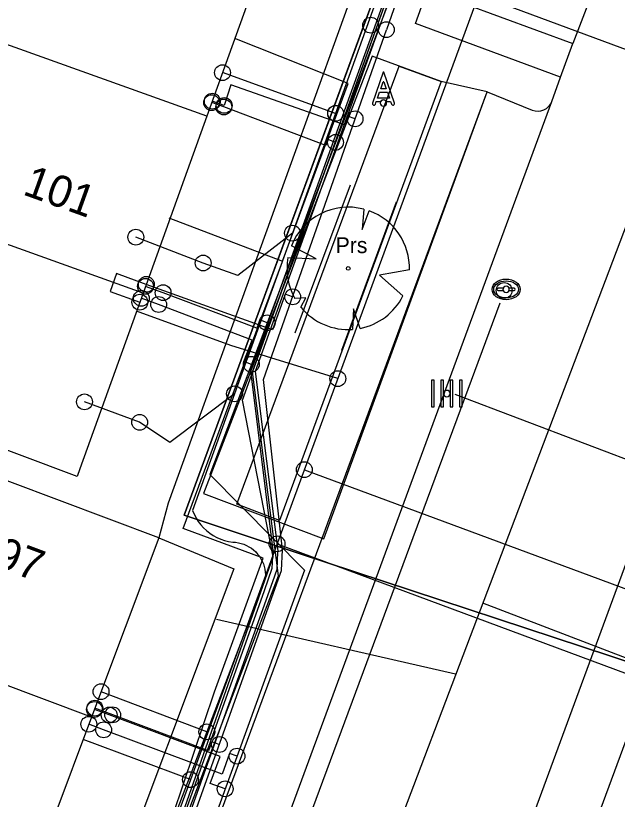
# Model space of a CAD drawing. Extents: x 192672 to 192910, y 446344 to 446512.
# Drawn here: x 192830.88 to 192849.9, y 446414.08 to 446438.86 of the extents above; entities that cross this region are included whole.
import ezdxf

# ---------------------------------------------------------------- set-up
doc = ezdxf.new("R2010")
doc.units = 0
for name, color, linetype in [('205134 wortelgeleidingsscherm', 7, 'Continuous'), ('B-GV-KG-GRENS_WERKGRENS-G', 7, 'Continuous'), ('B-OI-KL-()_MANTELBUIS_WATER-G', 7, 'Continuous'), ('B-OI-KL-()_OVERIG_RIOOLVRIJVERVAL-S', 7, 'Continuous'), ('B-OI-KL-()_PUNTVANLEVERING_WATER-S', 7, 'Continuous'), ('B-OI-KL-BUISLEIDING_OLIEGASCHEMICALIEN_GASLAGEDRUK-G', 7, 'Continuous'), ('B-OI-KL-DATA-G', 7, 'Continuous'), ('B-OI-KL-DATA_DUCT-G', 7, 'Continuous'), ('B-OI-KL-DATA_GTWP-S', 7, 'Continuous'), ('B-OI-KL-DATA_KABELBED-G', 7, 'Continuous'), ('B-OI-KL-DATA_MANTELBUIS-G', 7, 'Continuous'), ('B-OI-KL-DATA_MOF-S', 7, 'Continuous'), ('B-OI-KL-ET_LS-G', 7, 'Continuous'), ('B-OI-KL-ET_LS_AARDING-S', 7, 'Continuous'), ('B-OI-KL-ET_LS_DELIVERYPOINT-S', 7, 'Continuous'), ('B-OI-KL-ET_LS_MOF-S', 7, 'Continuous'), ('B-OI-KL-ET_MS-G', 7, 'Continuous'), ('B-OI-KL-GAS_LD_AFTAKZADEL-S', 7, 'Continuous'), ('B-OI-KL-GAS_LD_DELIVERYPOINT-S', 7, 'Continuous'), ('B-OI-KL-GAS_LD_OVERGANGSSTUK-S', 7, 'Continuous'), ('B-OI-KL-WATER-G', 7, 'Continuous'), ('B-OI-RI-RIOOLVRIJVERVAL-G', 7, 'Continuous'), ('bovenleidingmast', 7, 'Continuous'), ('Default', 7, 'Continuous'), ('huisnummerreeks BGT', 7, 'Continuous'), ('inspectie-   rioolput', 7, 'Continuous'), ('kant open verharding', 7, 'Continuous'), ('kant verharding', 7, 'Continuous'), ('kolk', 7, 'Continuous'), ('N-GV-GR-BOOM-S', 7, 'Continuous'), ('pand op maaiveld vlak', 7, 'Continuous'), ('TEKST', 7, 'Continuous'), ('verkeerseiland - berm', 7, 'Continuous')]:
    doc.layers.add(name, color=color, linetype=linetype)

# ---------------------------------------------------------------- blocks, each defined once
blk = doc.blocks.new('B-OI-KL-ET_LS_AARDING-S')
at = {"layer": 'Default'}
blk.add_circle((0, 0), 0.25, dxfattribs=at)
blk = doc.blocks.new('B-OI-KL-GAS_LD_AFTAKZADEL-S')
at = {"layer": 'Default'}
blk.add_circle((0, 0), 0.25, dxfattribs=at)
blk = doc.blocks.new('B-OI-KL-GAS_LD_DELIVERYPOINT-S')
at = {"layer": 'Default'}
blk.add_circle((0, 0), 0.25, dxfattribs=at)
blk = doc.blocks.new('B-OI-KL-GAS_LD_OVERGANGSSTUK-S')
at = {"layer": 'Default'}
blk.add_circle((0, 0), 0.25, dxfattribs=at)
blk = doc.blocks.new('B-OI-KL-ET_LS_DELIVERYPOINT-S')
at = {"layer": 'Default'}
blk.add_circle((0, 0), 0.25, dxfattribs=at)
blk = doc.blocks.new('B-OI-KL-ET_LS_MOF-S')
at = {"layer": 'Default'}
blk.add_circle((0, 0), 0.25, dxfattribs=at)
blk = doc.blocks.new('B-OI-KL-()_OVERIG_RIOOLVRIJVERVAL-S')
at = {"layer": 'Default'}
blk.add_circle((0, 0), 0.25, dxfattribs=at)
blk = doc.blocks.new('B-OI-KL-()_PUNTVANLEVERING_WATER-S')
at = {"layer": 'Default'}
blk.add_circle((0, 0), 0.25, dxfattribs=at)
blk = doc.blocks.new('B-OI-KL-DATA_GTWP-S')
at = {"layer": 'Default'}
blk.add_circle((0, 0), 0.25, dxfattribs=at)
blk = doc.blocks.new('B-OI-KL-DATA_MOF-S')
at = {"layer": 'Default'}
blk.add_circle((0, 0), 0.25, dxfattribs=at)

msp = doc.modelspace()

# ---------------------------------------------------------------- linework, layer by layer
at = {"layer": '205134 wortelgeleidingsscherm'}
for p, q in [((192839.712, 446428.827), (192841.461, 446433.511)), ((192841.184, 446428.282), (192842.919, 446432.971))]:
    msp.add_line(p, q, dxfattribs=at)
at = {"layer": 'B-GV-KG-GRENS_WERKGRENS-G'}
msp.add_lwpolyline([(192845.78, 446436.459), (192844.328, 446436.785), (192842.142, 446437.586), (192836.819, 446423.746), (192840.619, 446422.317)], close=True, dxfattribs=at)
at = {"layer": 'B-OI-KL-()_MANTELBUIS_WATER-G'}
msp.add_lwpolyline([(192833.29, 446415.867), (192833.01, 446415.972)], dxfattribs=at)
at = {"layer": 'B-OI-KL-BUISLEIDING_OLIEGASCHEMICALIEN_GASLAGEDRUK-G'}
for points in [[(192845.453, 446447.8), (192843.453, 446441.374), (192837.009, 446424.35), (192840.007, 446421.325), (192825.926, 446382.49)], [(192837.458, 446435.976), (192837.074, 446436.114)], [(192840.985, 446434.855), (192840.751, 446434.944), (192840.681, 446434.757), (192837.458, 446435.976)], [(192835.536, 446430.102), (192834.981, 446430.302)], [(192838.826, 446429.15), (192838.592, 446429.239), (192838.495, 446428.982), (192835.536, 446430.102)], [(192835.395, 446429.727), (192834.846, 446429.925)], [(192838.327, 446427.834), (192838.094, 446427.922), (192838.351, 446428.602), (192835.395, 446429.727)], [(192833.833, 446416.744), (192833.365, 446416.919)], [(192837.499, 446414.408), (192837.029, 446414.578), (192837.337, 446415.43), (192833.833, 446416.744)], [(192833.657, 446416.275), (192833.189, 446416.451)], [(192837.874, 446415.443), (192837.639, 446415.528), (192837.401, 446414.872), (192833.657, 446416.275)]]:
    msp.add_lwpolyline(points, dxfattribs=at)
at = {"layer": 'B-OI-KL-DATA-G'}
for points in [[(192821.742, 446509.756), (192825.984, 446501.22), (192835.895, 446480.007), (192842.472, 446466.378), (192848.635, 446454.503), (192848.764, 446454.232), (192845.185, 446446.654), (192842.489, 446440.231), (192836.203, 446423.068)], [(192821.742, 446509.756), (192825.984, 446501.22), (192835.895, 446480.007), (192842.472, 446466.378), (192848.635, 446454.503), (192848.764, 446454.232), (192845.185, 446446.654), (192842.489, 446440.231), (192836.203, 446423.068), (192839.811, 446421.866), (192851.515, 446418.004), (192854.977, 446417.712)], [(192821.742, 446509.756), (192825.984, 446501.22), (192835.895, 446480.007), (192842.472, 446466.378), (192848.635, 446454.503), (192848.764, 446454.232), (192845.185, 446446.654), (192842.489, 446440.231), (192836.203, 446423.068)], [(192821.742, 446509.756), (192825.984, 446501.22), (192835.895, 446480.007), (192842.472, 446466.378), (192848.635, 446454.503), (192848.764, 446454.232), (192845.185, 446446.654), (192842.489, 446440.231), (192836.203, 446423.068)], [(192821.742, 446509.756), (192825.984, 446501.22), (192835.895, 446480.007), (192842.472, 446466.378), (192848.635, 446454.503), (192848.764, 446454.232), (192845.185, 446446.654), (192842.489, 446440.231), (192836.203, 446423.068)], [(192821.742, 446509.756), (192825.984, 446501.22), (192835.895, 446480.007), (192842.472, 446466.378), (192848.635, 446454.503), (192848.764, 446454.232), (192845.185, 446446.654), (192842.489, 446440.231), (192836.203, 446423.068)], [(192821.742, 446509.756), (192825.984, 446501.22), (192835.895, 446480.007), (192842.472, 446466.378), (192848.635, 446454.503), (192848.764, 446454.232), (192845.185, 446446.654), (192842.489, 446440.231), (192836.203, 446423.068)], [(192821.742, 446509.756), (192825.984, 446501.22), (192835.895, 446480.007), (192842.472, 446466.378), (192848.635, 446454.503), (192848.764, 446454.232), (192845.185, 446446.654), (192842.489, 446440.231), (192836.203, 446423.068)], [(192821.742, 446509.756), (192825.984, 446501.22), (192835.895, 446480.007), (192842.472, 446466.378), (192848.635, 446454.503), (192848.764, 446454.232), (192845.185, 446446.654), (192842.489, 446440.231), (192836.203, 446423.068)], [(192675.743, 446430.36), (192720.2, 446413.771), (192739.906, 446406.53), (192752.421, 446411.058), (192770.152, 446404.44), (192773.577, 446403.064), (192825.629, 446383.71), (192826.856, 446388.539), (192834.171, 446407.983), (192839.017, 446421.742), (192838.042, 446426.7), (192842.865, 446440.095), (192846.683, 446450.008), (192848.26, 446453.903), (192848.365, 446454.374), (192848.254, 446454.945), (192844.011, 446462.681), (192860.643, 446470.952)], [(192854.977, 446417.712), (192851.515, 446418.004), (192839.811, 446421.866), (192836.203, 446423.068), (192842.489, 446440.231), (192845.185, 446446.654), (192847.347, 446451.231), (192841.744, 446449.857)], [(192854.977, 446417.712), (192851.515, 446418.004), (192839.811, 446421.866), (192836.203, 446423.068), (192842.489, 446440.231), (192845.185, 446446.654), (192847.347, 446451.231), (192841.744, 446449.857)], [(192854.977, 446417.712), (192851.515, 446418.004), (192839.811, 446421.866), (192836.203, 446423.068), (192842.489, 446440.231), (192845.185, 446446.654), (192847.347, 446451.231), (192841.744, 446449.857)], [(192854.977, 446417.712), (192851.515, 446418.004), (192839.811, 446421.866), (192836.203, 446423.068), (192842.489, 446440.231), (192845.185, 446446.654), (192847.347, 446451.231), (192841.744, 446449.857)], [(192854.977, 446417.712), (192851.515, 446418.004), (192839.811, 446421.866), (192836.203, 446423.068), (192842.489, 446440.231), (192845.185, 446446.654), (192847.347, 446451.231), (192841.744, 446449.857)], [(192854.977, 446417.712), (192851.515, 446418.004), (192839.811, 446421.866), (192836.203, 446423.068), (192842.489, 446440.231), (192845.185, 446446.654), (192847.347, 446451.231), (192841.744, 446449.857)], [(192854.977, 446417.712), (192851.515, 446418.004), (192839.811, 446421.866), (192836.203, 446423.068), (192842.489, 446440.231), (192845.185, 446446.654), (192847.347, 446451.231), (192841.744, 446449.857)], [(192854.977, 446417.712), (192851.515, 446418.004), (192839.811, 446421.866), (192836.203, 446423.068), (192842.489, 446440.231), (192845.185, 446446.654), (192847.347, 446451.231), (192841.744, 446449.857)], [(192841.819, 446438.402), (192836.203, 446423.068)], [(192839.312, 446431.096), (192841.391, 446436.713), (192837.803, 446438.139)], [(192835.72, 446432.47), (192839.312, 446431.096)], [(192837.627, 446426.579), (192839.307, 446431.084)], [(192839.307, 446431.084), (192839.312, 446431.096)], [(192839.051, 446430.844), (192836.203, 446423.068)], [(192837.162, 446417.48), (192838.705, 446421.7), (192836.174, 446422.641), (192837.627, 446426.579)], [(192836.878, 446424.911), (192836.203, 446423.068)], [(192835.526, 446412.626), (192837.162, 446417.48)]]:
    msp.add_lwpolyline(points, dxfattribs=at)
at = {"layer": 'B-OI-KL-DATA_DUCT-G'}
msp.add_lwpolyline([(192839.811, 446421.866), (192851.515, 446418.004)], dxfattribs=at)
at = {"layer": 'B-OI-KL-DATA_KABELBED-G'}
for points in [[(192846.984, 446450.462), (192845.185, 446446.654), (192842.489, 446440.231), (192841.819, 446438.402)], [(192842.583, 446440.196), (192840.99, 446435.774), (192839.625, 446431.983), (192837.795, 446426.902), (192836.468, 446423.216), (192836.518, 446423.095), (192836.578, 446422.978), (192836.648, 446422.867), (192836.727, 446422.763), (192836.815, 446422.665), (192836.91, 446422.576), (192837.013, 446422.495), (192837.123, 446422.423), (192837.238, 446422.36), (192837.358, 446422.308), (192837.482, 446422.266), (192837.609, 446422.234), (192837.739, 446422.214), (192837.829, 446422.208), (192837.918, 446422.194), (192838.005, 446422.173), (192838.09, 446422.145), (192838.173, 446422.109), (192838.252, 446422.067), (192838.328, 446422.018), (192838.399, 446421.963), (192838.465, 446421.902), (192838.526, 446421.835), (192838.58, 446421.764), (192838.629, 446421.688), (192838.671, 446421.609), (192838.706, 446421.526), (192838.734, 446421.44), (192838.755, 446421.353), (192838.768, 446421.264), (192838.773, 446421.174), (192838.771, 446421.084), (192836.919, 446416.21), (192835.278, 446411.894)], [(192841.819, 446438.402), (192839.051, 446430.844)], [(192840.99, 446435.774), (192837.416, 446437.062)], [(192836.802, 446431.04), (192834.676, 446431.859)], [(192839.625, 446431.983), (192837.894, 446430.643), (192836.802, 446431.04)], [(192839.051, 446430.844), (192836.878, 446424.911)], [(192837.795, 446426.902), (192835.75, 446425.366), (192834.795, 446426.001)], [(192834.795, 446426.001), (192833.05, 446426.647)], [(192836.878, 446424.911), (192836.203, 446423.068)], [(192836.203, 446423.068), (192839.811, 446421.866)], [(192839.811, 446421.866), (192851.515, 446418.004)], [(192836.919, 446416.21), (192833.575, 446417.481)]]:
    msp.add_lwpolyline(points, dxfattribs=at)
at = {"layer": 'B-OI-KL-DATA_MANTELBUIS-G'}
msp.add_lwpolyline([(192839.811, 446421.866), (192851.515, 446418.004)], dxfattribs=at)
at = {"layer": 'B-OI-KL-ET_LS-G'}
for points in [[(192860.643, 446470.819), (192853.82, 446467.429), (192844.159, 446462.832), (192848.319, 446454.352), (192847.996, 446450.764), (192844.729, 446444.056), (192843.125, 446439.931), (192842.595, 446438.42)], [(192860.643, 446470.651), (192853.885, 446467.294), (192845.216, 446463.169), (192844.43, 446462.795), (192844.044, 446462.611), (192844.191, 446462.302), (192845.901, 446458.82), (192848.033, 446454.48), (192848.021, 446454.392), (192847.702, 446450.846), (192844.451, 446444.169), (192842.774, 446440.064), (192838.296, 446427.628), (192839.011, 446421.946), (192838.979, 446421.373), (192838.731, 446420.673), (192837.083, 446416.058), (192835.6, 446411.903), (192834.188, 446408.031), (192832.801, 446404.329), (192833.741, 446403.977)], [(192842.917, 446440.019), (192838.449, 446427.611), (192839.163, 446421.938), (192839.166, 446421.912), (192839.152, 446421.889), (192839.128, 446421.343), (192838.992, 446420.96), (192837.204, 446415.951), (192835.748, 446411.871), (192834.426, 446408.238), (192832.994, 446404.416), (192833.787, 446404.119)], [(192751.683, 446410.693), (192751.864, 446410.643), (192755.959, 446409.097), (192774.392, 446402.333), (192793.329, 446395.227), (192810.936, 446388.57), (192825.501, 446383.221), (192828.633, 446391.683), (192830.747, 446397.998), (192835.074, 446409.537), (192839.277, 446421.313), (192839.311, 446421.965), (192838.716, 446427.358), (192842.595, 446438.42)], [(192841.606, 446435.601), (192841.37, 446435.684), (192841.273, 446435.406), (192837.682, 446436.681), (192837.466, 446436.025)], [(192837.466, 446436.025), (192837.091, 446436.16)], [(192835.004, 446430.364), (192834.063, 446430.703), (192833.86, 446430.139), (192834.8, 446429.8)], [(192839.632, 446429.97), (192839.396, 446430.053), (192839, 446428.925), (192835.004, 446430.364)], [(192833.942, 446416.75), (192833.38, 446416.961)], [(192837.313, 446415.809), (192837.077, 446415.893), (192836.977, 446415.612), (192833.942, 446416.75)]]:
    msp.add_lwpolyline(points, dxfattribs=at)
at = {"layer": 'B-OI-KL-ET_MS-G'}
msp.add_lwpolyline([(192806.764, 446390.772), (192825.096, 446383.91), (192826.671, 446388.028), (192834.794, 446409.643), (192839.188, 446421.141), (192838.367, 446427.603), (192842.844, 446440.037), (192844.587, 446444.106), (192847.849, 446450.805), (192847.991, 446451.236), (192848.111, 446451.673), (192848.209, 446452.116), (192848.285, 446452.564), (192848.339, 446453.014), (192848.37, 446453.467), (192848.378, 446453.921), (192848.364, 446454.374), (192844.011, 446462.68), (192853.853, 446467.362), (192860.643, 446470.735)], dxfattribs=at)
at = {"layer": 'B-OI-KL-WATER-G'}
for points in [[(192826.018, 446386.448), (192827.039, 446389.193), (192849.599, 446450.644)], [(192858.635, 446434.656), (192845.516, 446439.523)], [(192841.06, 446427.384), (192837.683, 446428.436), (192834.697, 446429.512)], [(192840.002, 446424.503), (192855.51, 446418.747)], [(192839.14, 446422.156), (192854.64, 446416.402)], [(192836.403, 446414.7), (192833.01, 446415.972)]]:
    msp.add_lwpolyline(points, dxfattribs=at)
at = {"layer": 'B-OI-RI-RIOOLVRIJVERVAL-G'}
for points in [[(192855.92, 446447.38), (192840.05, 446405.53)], [(192846.181, 446429.773), (192836.26, 446402.977)], [(192850.938, 446424.54), (192844.768, 446426.882)], [(192845.639, 446420.294), (192852.866, 446417.516)], [(192844.786, 446418.04), (192837.22, 446419.76)]]:
    msp.add_lwpolyline(points, dxfattribs=at)
at = {"layer": 'bovenleidingmast'}
for p, q in [((192842.495, 446437.072), (192842.154, 446436.099)), ((192842.854, 446436.099), (192842.513, 446437.072))]:
    msp.add_line(p, q, dxfattribs=at)
for points in [[(192842.513, 446436.769), (192842.591, 446436.549), (192842.417, 446436.549), (192842.495, 446436.769)], [(192842.248, 446436.066), (192842.277, 446436.149), (192842.417, 446436.149)], [(192842.591, 446436.149), (192842.731, 446436.149), (192842.76, 446436.066)]]:
    msp.add_lwpolyline(points, dxfattribs=at)
msp.add_lwpolyline([(192842.626, 446436.449), (192842.696, 446436.249), (192842.312, 446436.249), (192842.382, 446436.449)], close=True, dxfattribs=at)
for centre, radius, start, end in [((192842.504, 446437.069), 0.01, 19.29, 160.71), ((192842.504, 446436.766), 0.01, 19.29, 160.71), ((192842.201, 446436.082), 0.05, 160.71, 340.71), ((192842.504, 446436.099), 0.1, 0, 180), ((192842.504, 446436.099), 0.1, 180, 0), ((192842.504, 446436.099), 0.1, 30, 150), ((192842.807, 446436.082), 0.05, 199.29, 19.29)]:
    msp.add_arc(centre, radius, start, end, dxfattribs=at)
at = {"layer": 'inspectie-   rioolput'}
for p, q in [((192846.289, 446430.243), (192846.132, 446430.243)), ((192846.132, 446430.169), (192846.289, 446430.169)), ((192846.632, 446430.243), (192846.475, 446430.243)), ((192846.475, 446430.169), (192846.632, 446430.169))]:
    msp.add_line(p, q, dxfattribs=at)
for centre, radius, start, end in [((192846.132, 446430.206), 0.0375, 90, 270), ((192846.382, 446430.206), 0.1, 0, 180), ((192846.382, 446430.206), 0.1, 157.9757, 180), ((192846.382, 446430.206), 0.1, 180, 202.0243), ((192846.382, 446430.206), 0.1, 180, 0), ((192846.382, 446430.206), 0.1, 0, 22.0243), ((192846.382, 446430.206), 0.1, 337.9757, 0), ((192846.632, 446430.206), 0.0375, 270, 90)]:
    msp.add_arc(centre, radius, start, end, dxfattribs=at)
for major_axis, ratio in [((-0.442, 0), 0.73911), ((-0.392, 0), 0.689655)]:
    msp.add_ellipse((192846.382, 446430.206), major_axis=major_axis, ratio=ratio, dxfattribs=at)
at = {"layer": 'kant open verharding'}
msp.add_line((192847.824, 446436.149), (192848.102, 446436.917), dxfattribs=at)
for points in [[(192846.946, 446454.816), (192845.635, 446451.129), (192845.293, 446450.169), (192841.851, 446440.492), (192835.693, 446423.446), (192835.401, 446422.35)], [(192848.102, 446436.917), (192843.514, 446438.619), (192843.896, 446439.682), (192848.491, 446437.98)], [(192835.401, 446422.35), (192837.776, 446421.364), (192833.548, 446410.11)]]:
    msp.add_lwpolyline(points, dxfattribs=at)
at = {"layer": 'kant verharding'}
for p, q in [((192849.014, 446439.367), (192848.491, 446437.98)), ((192848.102, 446436.917), (192848.491, 446437.98)), ((192835.879, 446403.721), (192847.824, 446436.149)), ((192854.067, 446432.141), (192842.706, 446401.261))]:
    msp.add_line(p, q, dxfattribs=at)
for points in [[(192835.578, 446404.274), (192834.092, 446404.819), (192845.78, 446436.459), (192847.207, 446435.879)], [(192854.375, 446431.535), (192855.749, 446431.055), (192844.653, 446401.014), (192843.315, 446401.529)]]:
    msp.add_lwpolyline(points, dxfattribs=at)
msp.add_arc((192847.381, 446436.321), 0.475, 248.5093, 338.7592, dxfattribs=at)
at = {"layer": 'kolk'}
for points in [[(192844.104, 446426.912), (192844.104, 446427.337), (192844.019, 446427.337), (192844.019, 446426.912), (192844.019, 446426.487), (192844.104, 446426.487)], [(192844.402, 446426.912), (192844.402, 446427.337), (192844.317, 446427.337), (192844.317, 446426.912), (192844.317, 446426.487), (192844.402, 446426.487)], [(192844.699, 446426.912), (192844.699, 446427.337), (192844.614, 446427.337), (192844.614, 446426.912), (192844.614, 446426.487), (192844.699, 446426.487)], [(192844.997, 446426.912), (192844.997, 446427.337), (192844.912, 446427.337), (192844.912, 446426.912), (192844.912, 446426.487), (192844.997, 446426.487)]]:
    msp.add_lwpolyline(points, close=True, dxfattribs=at)
for start, end in [(0, 180), (180, 0)]:
    msp.add_arc((192844.508, 446426.912), 0.1, start, end, dxfattribs=at)
at = {"layer": 'N-GV-GR-BOOM-S'}
for points in [[(192841.885, 446432.742), (192841.828, 446432.103), (192842.056, 446432.688)], [(192839.485, 446431.214), (192840.379, 446431.172), (192839.591, 446431.586)], [(192843.326, 446430.82), (192842.376, 446430.658), (192843.119, 446429.997)], [(192839.891, 446429.644), (192840.044, 446429.94), (192839.704, 446429.918)], [(192841.772, 446428.971), (192841.552, 446429.589), (192841.529, 446428.938)]]:
    msp.add_lwpolyline(points, dxfattribs=at)
msp.add_circle((192841.39, 446430.87), 0.0577, dxfattribs=at)
for start, end in [(75.1844, 158.299), (358.5241, 69.9066), (169.749, 209.4302), (281.3601, 333.2046), (219.2667, 274.1068)]:
    msp.add_arc((192841.39, 446430.87), 1.936, start, end, dxfattribs=at)
at = {"layer": 'pand op maaiveld vlak'}
for p, q in [((192836.921, 446435.689), (192829.917, 446438.195)), ((192836.921, 446435.689), (192834.902, 446430.082)), ((192834.902, 446430.082), (192827.856, 446432.619)), ((192835.401, 446422.35), (192833.275, 446416.68)), ((192833.275, 446416.68), (192825.41, 446419.628)), ((192833.275, 446416.68), (192831.149, 446411.009))]:
    msp.add_line(p, q, dxfattribs=at)
for points in [[(192838.693, 446441.612), (192839.008, 446441.484), (192836.921, 446435.689)], [(192834.902, 446430.082), (192832.903, 446424.53), (192832.816, 446424.287), (192825.772, 446426.935), (192827.165, 446430.802), (192827.856, 446432.619)], [(192835.401, 446422.35), (192827.536, 446425.299), (192827.428, 446425.012), (192825.41, 446419.628)]]:
    msp.add_lwpolyline(points, dxfattribs=at)
at = {"layer": 'verkeerseiland - berm'}
msp.add_lwpolyline([(192844.328, 446436.785), (192839.219, 446422.899), (192837.863, 446423.41), (192842.999, 446437.265), (192844.328, 446436.785)], dxfattribs=at)

# ---------------------------------------------------------------- block references
at = {"layer": 'B-OI-KL-()_OVERIG_RIOOLVRIJVERVAL-S'}
msp.add_blockref('B-OI-KL-()_OVERIG_RIOOLVRIJVERVAL-S', (192846.32, 446430.17), dxfattribs=at)
at = {"layer": 'B-OI-KL-()_PUNTVANLEVERING_WATER-S'}
for p in [(192841.06, 446427.384), (192840.002, 446424.503), (192839.14, 446422.156), (192836.403, 446414.7)]:
    msp.add_blockref('B-OI-KL-()_PUNTVANLEVERING_WATER-S', p, dxfattribs=at)
at = {"layer": 'B-OI-KL-DATA_GTWP-S'}
for p in [(192837.416, 446437.062), (192840.99, 446435.774), (192834.676, 446431.859), (192839.625, 446431.983), (192836.802, 446431.04), (192836.802, 446431.04), (192837.795, 446426.902), (192833.05, 446426.647), (192834.795, 446426.001), (192834.795, 446426.001), (192833.575, 446417.481), (192836.919, 446416.21)]:
    msp.add_blockref('B-OI-KL-DATA_GTWP-S', p, dxfattribs=at)
at = {"layer": 'B-OI-KL-DATA_MOF-S'}
for p in [(192840.991, 446435.774), (192839.625, 446431.983), (192836.802, 446431.04), (192837.796, 446426.902), (192834.795, 446426.001), (192836.919, 446416.21)]:
    msp.add_blockref('B-OI-KL-DATA_MOF-S', p, dxfattribs=at)
at = {"layer": 'B-OI-KL-ET_LS_AARDING-S'}
msp.add_blockref('B-OI-KL-ET_LS_AARDING-S', (192842.101, 446438.563), dxfattribs=at)
at = {"layer": 'B-OI-KL-ET_LS_DELIVERYPOINT-S'}
for p in [(192837.091, 446436.16), (192835.004, 446430.364), (192834.8, 446429.8), (192833.38, 446416.961)]:
    msp.add_blockref('B-OI-KL-ET_LS_DELIVERYPOINT-S', p, dxfattribs=at)
at = {"layer": 'B-OI-KL-ET_LS_MOF-S'}
for p in [(192842.595, 446438.42), (192837.466, 446436.025), (192841.606, 446435.601), (192839.632, 446429.97), (192833.942, 446416.75), (192837.313, 446415.809)]:
    msp.add_blockref('B-OI-KL-ET_LS_MOF-S', p, dxfattribs=at)
at = {"layer": 'B-OI-KL-GAS_LD_AFTAKZADEL-S'}
for p in [(192840.985, 446434.855), (192838.826, 446429.15), (192838.327, 446427.834), (192837.874, 446415.443), (192837.499, 446414.408)]:
    msp.add_blockref('B-OI-KL-GAS_LD_AFTAKZADEL-S', p, dxfattribs=at)
at = {"layer": 'B-OI-KL-GAS_LD_DELIVERYPOINT-S'}
for p in [(192837.074, 446436.114), (192834.981, 446430.302), (192834.846, 446429.925), (192833.365, 446416.919), (192833.189, 446416.451)]:
    msp.add_blockref('B-OI-KL-GAS_LD_DELIVERYPOINT-S', p, dxfattribs=at)
at = {"layer": 'B-OI-KL-GAS_LD_OVERGANGSSTUK-S'}
for p in [(192837.458, 446435.976), (192835.536, 446430.102), (192835.395, 446429.727), (192833.833, 446416.744), (192833.657, 446416.275)]:
    msp.add_blockref('B-OI-KL-GAS_LD_OVERGANGSSTUK-S', p, dxfattribs=at)

# ---------------------------------------------------------------- texts
at = {"layer": 'huisnummerreeks BGT'}
for s, rotation, p in [('101', 340.2, (192831.064, 446433.219)), ('97', 339.5, (192830.146, 446421.47))]:
    msp.add_text(s, height=1, rotation=rotation, dxfattribs=at).set_placement(p)
at = {"layer": 'TEKST'}
msp.add_text('Prs', height=0.5, dxfattribs=at).set_placement((192840.993, 446431.353))

doc.saveas('drawing.dxf')
